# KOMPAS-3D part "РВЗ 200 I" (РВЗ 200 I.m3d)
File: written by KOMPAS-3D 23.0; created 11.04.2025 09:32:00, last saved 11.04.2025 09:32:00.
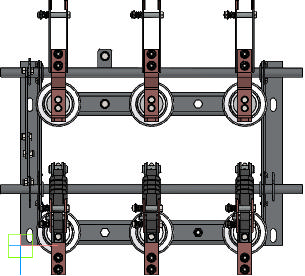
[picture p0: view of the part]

Document properties: Автор: pc; Полное имя файла: C:\Users\pc\Desktop\работа\РВЗ\3D макеты\РВЗ 200 I.m3d

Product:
- Body: Тело 1
    Масса: 1.60238
- Body: Тело 2
    Масса: 0.011176
- Body: Тело 3
    Масса: 0.011176
- Body: Тело 4
    Масса: 1.60238
- Part/product: РВЗ 200 I
    Масса: 3.227111

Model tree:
1. Операция без истории:1
2. Операция без истории:2
3. Операция без истории:3
4. Операция без истории:4
5. Поверхность без истории:1
6. Поверхность без истории:2
7. Поверхность без истории:3
8. Поверхность без истории:4
9. Поверхность без истории:5
10. Поверхность без истории:6
11. Поверхность без истории:7
12. Поверхность без истории:8
13. Поверхность без истории:9
14. Поверхность без истории:10
15. Поверхность без истории:11
16. Поверхность без истории:12
17. Поверхность без истории:13
18. Поверхность без истории:14
19. Поверхность без истории:15
20. Поверхность без истории:16
21. Поверхность без истории:17
22. Поверхность без истории:18
23. Поверхность без истории:19
24. Поверхность без истории:20
25. Поверхность без истории:21
26. Поверхность без истории:22
27. Поверхность без истории:23
28. Поверхность без истории:24
29. Поверхность без истории:25
30. Поверхность без истории:26
31. Поверхность без истории:27
32. Поверхность без истории:28
33. Поверхность без истории:29
34. Поверхность без истории:30
35. Поверхность без истории:31
36. Поверхность без истории:32
37. Поверхность без истории:33
38. Поверхность без истории:34
39. Поверхность без истории:35
40. Поверхность без истории:36
41. Поверхность без истории:37
42. Поверхность без истории:38
43. Поверхность без истории:39
44. Поверхность без истории:40
45. Поверхность без истории:41
46. Поверхность без истории:42
47. Поверхность без истории:43
48. Поверхность без истории:44
49. Поверхность без истории:45
50. Поверхность без истории:46
51. Поверхность без истории:47
52. Поверхность без истории:48
53. Поверхность без истории:49
54. Поверхность без истории:50
55. Поверхность без истории:51
56. Поверхность без истории:52
57. Поверхность без истории:53
58. Поверхность без истории:54
59. Поверхность без истории:55
60. Поверхность без истории:56
61. Поверхность без истории:57
62. Поверхность без истории:58
63. Поверхность без истории:59
64. Поверхность без истории:60
65. Поверхность без истории:61
66. Поверхность без истории:62
67. Поверхность без истории:63
68. Поверхность без истории:64
69. Поверхность без истории:65
70. Поверхность без истории:66
71. Поверхность без истории:67
72. Поверхность без истории:68
73. Поверхность без истории:69
74. Поверхность без истории:70
75. Поверхность без истории:71
76. Поверхность без истории:72
77. Поверхность без истории:73
78. Поверхность без истории:74
79. Поверхность без истории:75
80. Поверхность без истории:76
81. Поверхность без истории:77
82. Поверхность без истории:78
83. Поверхность без истории:79
84. Поверхность без истории:80
85. Поверхность без истории:81
86. Поверхность без истории:82
87. Поверхность без истории:83
88. Поверхность без истории:84
89. Поверхность без истории:85
90. Поверхность без истории:86
91. Поверхность без истории:87
92. Поверхность без истории:88
93. Поверхность без истории:89
94. Поверхность без истории:90
95. Поверхность без истории:91
96. Поверхность без истории:92
97. Поверхность без истории:93
98. Поверхность без истории:94
99. Поверхность без истории:95
100. Поверхность без истории:96
101. Поверхность без истории:97
102. Поверхность без истории:98
103. Поверхность без истории:99
104. Поверхность без истории:100
105. Поверхность без истории:101
106. Поверхность без истории:102
107. Поверхность без истории:103
108. Поверхность без истории:104
109. Поверхность без истории:105
110. Поверхность без истории:106
111. Поверхность без истории:107
112. Поверхность без истории:108
113. Поверхность без истории:109
114. Поверхность без истории:110
115. Поверхность без истории:111
116. Поверхность без истории:112
117. Поверхность без истории:113
118. Поверхность без истории:114
119. Поверхность без истории:115
120. Поверхность без истории:116
121. Поверхность без истории:117
122. Поверхность без истории:118
123. Поверхность без истории:119
124. Поверхность без истории:120
125. Поверхность без истории:121
126. Поверхность без истории:122
127. Поверхность без истории:123
128. Поверхность без истории:124
129. Поверхность без истории:125
130. Поверхность без истории:126
131. Поверхность без истории:127
132. Поверхность без истории:128
133. Поверхность без истории:129
134. Поверхность без истории:130
135. Поверхность без истории:131
136. Поверхность без истории:132
137. Поверхность без истории:133
138. Поверхность без истории:134
139. Поверхность без истории:135
140. Поверхность без истории:136
141. Поверхность без истории:137
142. Поверхность без истории:138
143. Поверхность без истории:139
144. Поверхность без истории:140
145. Поверхность без истории:141
146. Поверхность без истории:142
147. Поверхность без истории:143
148. Поверхность без истории:144
149. Поверхность без истории:145
150. Поверхность без истории:146
151. Поверхность без истории:147
152. Поверхность без истории:148
153. Поверхность без истории:149
154. Поверхность без истории:150
155. Поверхность без истории:151
156. Поверхность без истории:152
157. Поверхность без истории:153
158. Поверхность без истории:154
159. Поверхность без истории:155
160. Поверхность без истории:156
161. Поверхность без истории:157
162. Поверхность без истории:158
163. Поверхность без истории:159
164. Поверхность без истории:160
165. Поверхность без истории:161
166. Поверхность без истории:162
167. Поверхность без истории:163
168. Поверхность без истории:164
169. Поверхность без истории:165
170. Поверхность без истории:166
171. Поверхность без истории:167
172. Поверхность без истории:168
173. Поверхность без истории:169
174. Поверхность без истории:170
175. Поверхность без истории:171
176. Поверхность без истории:172
177. Поверхность без истории:173
178. Поверхность без истории:174
179. Поверхность без истории:175
180. Поверхность без истории:176
181. Поверхность без истории:177
182. Поверхность без истории:178
183. Поверхность без истории:179
184. Поверхность без истории:180
185. Поверхность без истории:181
186. Поверхность без истории:182
187. Поверхность без истории:183
188. Поверхность без истории:184
189. Поверхность без истории:185
190. Поверхность без истории:186
191. Поверхность без истории:187
192. Поверхность без истории:188
193. Поверхность без истории:189
194. Поверхность без истории:190
195. Поверхность без истории:191
196. Поверхность без истории:192
197. Поверхность без истории:193
198. Поверхность без истории:194
199. Поверхность без истории:195
200. Поверхность без истории:196
201. Поверхность без истории:197
202. Поверхность без истории:198
203. Поверхность без истории:199
204. Поверхность без истории:200
205. Поверхность без истории:201
206. Поверхность без истории:202
207. Поверхность без истории:203
208. Поверхность без истории:204
209. Поверхность без истории:205
210. Поверхность без истории:206
211. Поверхность без истории:207
212. Поверхность без истории:208
213. Поверхность без истории:209
214. Поверхность без истории:210
215. Поверхность без истории:211
216. Поверхность без истории:212
217. Поверхность без истории:213
218. Поверхность без истории:214
219. Поверхность без истории:215
220. Поверхность без истории:216
221. Поверхность без истории:217
222. Поверхность без истории:218
223. Поверхность без истории:219
224. Поверхность без истории:220
225. Поверхность без истории:221
226. Поверхность без истории:222
227. Поверхность без истории:223
228. Поверхность без истории:224
229. Поверхность без истории:225
230. Поверхность без истории:226
231. Поверхность без истории:227
232. Поверхность без истории:228
233. Поверхность без истории:229
234. Поверхность без истории:230
235. Поверхность без истории:231
236. Поверхность без истории:232
237. Поверхность без истории:233
238. Поверхность без истории:234
239. Поверхность без истории:235
240. Поверхность без истории:236
241. Поверхность без истории:237
242. Поверхность без истории:238
243. Поверхность без истории:239
244. Поверхность без истории:240
245. Поверхность без истории:241
246. Поверхность без истории:242
247. Поверхность без истории:243
248. Поверхность без истории:244
249. Поверхность без истории:245
250. Поверхность без истории:246
251. Поверхность без истории:247
252. Поверхность без истории:248
253. Поверхность без истории:249
254. Поверхность без истории:250
255. Поверхность без истории:251
256. Поверхность без истории:252
257. Поверхность без истории:253
258. Поверхность без истории:254
259. Поверхность без истории:255
260. Поверхность без истории:256
261. Поверхность без истории:257
262. Поверхность без истории:258
263. Поверхность без истории:259
264. Поверхность без истории:260
265. Поверхность без истории:261
266. Поверхность без истории:262
267. Поверхность без истории:263
268. Поверхность без истории:264
269. Поверхность без истории:265
270. Поверхность без истории:266
271. Поверхность без истории:267
272. Поверхность без истории:268
273. Поверхность без истории:269
274. Поверхность без истории:270
275. Поверхность без истории:271
276. Поверхность без истории:272
277. Поверхность без истории:273
278. Поверхность без истории:274
279. Поверхность без истории:275
280. Поверхность без истории:276
281. Поверхность без истории:277
282. Поверхность без истории:278
283. Поверхность без истории:279
284. Поверхность без истории:280
285. Поверхность без истории:281
286. Поверхность без истории:282
287. Поверхность без истории:283
288. Поверхность без истории:284
289. Поверхность без истории:285
290. Поверхность без истории:286
291. Поверхность без истории:287
292. Поверхность без истории:288
293. Поверхность без истории:289
294. Поверхность без истории:290
295. Поверхность без истории:291
296. Поверхность без истории:292
297. Поверхность без истории:293
298. Поверхность без истории:294
299. Поверхность без истории:295
300. Поверхность без истории:296
301. Поверхность без истории:297
302. Поверхность без истории:298
303. Поверхность без истории:299
304. Поверхность без истории:300
305. Поверхность без истории:301
306. Поверхность без истории:302
307. Поверхность без истории:303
